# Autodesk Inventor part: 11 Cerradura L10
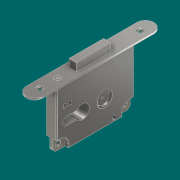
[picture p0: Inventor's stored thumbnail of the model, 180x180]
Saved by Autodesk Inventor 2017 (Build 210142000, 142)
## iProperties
Created: 2019-09
Part Number: 11 Cerradura L10
Material: Acero inoxidable
Document SubType Name: Modeling
Designer: Alfredo Castillo
Density: 8 g/cm^3
Appearance: Semipulido
Mass: 1146.85 g
Surface Area: 306.712 cm^2
Volume: 143.356 cm^3
Comments: Proveedor ITALINNEA Producto CERRADURA ADICIONAL REF. L10 CANTO REDONDO Marca AGB (ITALIA) Modelo L10 Canto Redondo Material ACERO ZINCADO Terminación BRONCE, NIQUELADA, BRONCEADA, BLACK MATT Y GRAFIT
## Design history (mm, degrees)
sketch "Boceto1"
  geometry: L1 (0, 0)-(0, 165); L2 (11, 11)-(11, 154); L3 (-11, 154)-(-11, 11); C1 r 2.75 at (0, 147.5); C2 r 2.75 at (0, 17.5); A1 r 11 centre (0, 11) between (-11, 11) and (11, 11); A2 r 11 centre (0, 154) between (11, 154) and (-11, 154); 1 further point
  constraints: 8 end point, 6 point on circle, 4 centre point, 4 point on line, 4 tangent, 1 midpoint, 1 parallel, 1 vertical
  dimensions: "d0" = 165 distance of L1.start L1.end; "d1" = 22 diameter of A2; "d2" = 5.5 diameter of C1; "d3" = 5.5 diameter of C2; "d187" = 130 distance of C2.centre C1.centre; "d188" = 17.5 distance of L1.start C2.centre
extrude "Extrusión1" new body sketch "Boceto1" distance "d6" = 3; taper "d7" = 0 deg
chamfer "Chaflán1" distance "d8" = 1.5; stored, may be unused: second distance "d9" = 2, angle "d10" = 45 deg
fillet "Empalme1" dims "d11" = 1
sketch "Boceto2"
  geometry: L1 (-7, 132.5)-(7, 132.5); L2 (7, 132.5)-(7, 32.5); L3 (7, 32.5)-(-7, 32.5); L4 (-7, 32.5)-(-7, 132.5); L5 (11, 11)-(11, 154) reference; 1 further point
  constraints: 8 end point, 2 parallel, 1 horizontal, 1 perpendicular
  dimensions: "d12" = 100 distance of L1.end L2.end; "d13" = 32.5 distance from line of point (0, 0) L3; "d16" = 14 distance of L1.start L1.end; "d17" = 4 distance between parallel lines of L5 L2
extrude "Extrusión2" join sketch "Boceto2" distance "d14" = 76; taper "d15" = 0 deg
sketch "Boceto3"
  geometry: L1 (0, 100)-(-76, 100) reference; L2 (-76, 0)-(-76, 100) reference; L3 (-76, 85)-(-76, 100); L4 (-76, 100)-(-61, 100); L5 (-76, 15)-(-76, 0); L6 (-76, 0)-(-61, 0); L7 (-76, 85)-(-71, 85); L8 (-61, 100)-(-61, 95); L9 (-76, 15)-(-71, 15); L10 (-61, 5)-(-61, 0); A1 r 10 centre (-71, 5) between (-61, 5) and (-71, 15); A2 r 10 centre (-71, 95) between (-71, 85) and (-61, 95); 1 further point
  constraints: 16 end point, 4 point on circle, 4 tangent, 3 perpendicular, 2 centre point, 2 collinear, 2 horizontal, 1 point on line, 1 vertical
  dimensions: "d254" = 5 distance of L4.end L8.end; "d255" = 10 radius of A2; "d256" = 5 distance of L3.start L7.end; "d257" = 5 distance of L5.start L9.end; "d258" = 5 distance of L10.start L6.end
extrude "Extrusión3" cut sketch "Boceto3" distance "d23" = 5; taper "d24" = 0 deg
sketch "Boceto5"
  geometry: L1 (0, 100)-(76, 100) reference; L2 (76, 100)-(76, 0) reference; L3 (61, 100)-(76, 100); L4 (76, 100)-(76, 85); L5 (76, 20)-(76, 0); L6 (76, 0)-(61, 0); L7 (0, 0)-(76, 0) reference; L8 (76, 85)-(71, 85); L9 (61, 95)-(61, 100); L10 (61, 0)-(61, 5); L11 (76, 0)-(76, 100) reference; L12 (61, 0)-(66, 0); L13 (71, 15)-(76, 15); A1 r 10 centre (71, 95) between (61, 95) and (71, 85); A2 r 10 centre (71, 5) between (71, 15) and (61, 5); 1 further point
  constraints: 18 end point, 4 point on circle, 3 collinear, 3 horizontal, 3 perpendicular, 3 point on line, 3 tangent, 2 centre point, 1 parallel
  dimensions: "d260" = 5 distance of L4.end L8.end; "d261" = 5 distance of L6.end L10.end; "d262" = 90 deg angle of L12 L10 (derived); "d263" = 5 distance of L13.start L13.end; "d264" = 10 radius of A2; "d265" = 5 distance from line of L2 A2.centre; "d266" = 5 distance of L9.start L3.start
extrude "Extrusión4" cut sketch "Boceto5" distance "d25" = 5; taper "d26" = 0 deg
fillet "Empalme2" dims "d27" = 5
hole "Agujero1" diameter "d31" = 5; stored, may be unused: countersink angle "d35" = 90 deg, drill point angle "d37" = 118 deg; dims "d29" = 7, "d30" = 7, "d32" = 6, "d33" = 4, "d34" = 2, "d36" = 8
hole "Agujero2" diameter "d40" = 5; stored, may be unused: countersink angle "d44" = 90 deg, drill point angle "d46" = 118 deg; dims "d38" = 7, "d39" = 7, "d41" = 6, "d42" = 4, "d43" = 2, "d45" = 8
fillet "Empalme4" dims "d47" = 1
fillet "Empalme5" dims "d48" = 1
fillet "Empalme6" dims "d49" = 1
fillet "Empalme7" dims "d50" = 1
sketch "Boceto37"
  geometry: L1 (-43.967, 6.834)-(-43.967, 32.334); L2 (-38.467, 12.334)-(-38.467, 25.21); L3 (-49.467, 25.21)-(-49.467, 12.334); A1 r 9 centre (-43.967, 32.334) between (-38.467, 25.21) and (-49.467, 25.21); A2 r 5.5 centre (-43.967, 12.334) between (-49.467, 12.334) and (-38.467, 12.334); 4 further points
  constraints: 8 end point, 5 point on circle, 2 centre point, 2 coincident, 2 tangent, 1 midpoint, 1 parallel, 1 point on line, 1 vertical
  dimensions: "d189" = 18 diameter of A1; "d190" = 20 distance of A2.centre A1.centre; "d191" = 10 distance of point (-43.967, 22.334) A1.centre; "d192" = 11 distance between parallel lines of L2 L3
extrude "Extrusión32" cut sketch "Boceto37" distance "d193" = 20; taper "d194" = 0 deg
sketch "Boceto38"
  geometry: L1 (-5, 105)-(5, 105); L2 (5, 105)-(5, 60); L3 (5, 60)-(-5, 60); L4 (-5, 60)-(-5, 105); L5 (11, 11)-(11, 154) reference; C1 r 2.75 at (0, 147.5) reference; 1 further point
  constraints: 8 end point, 2 parallel, 1 horizontal, 1 perpendicular
  dimensions: "d195" = 10 distance of L2.end L3.end; "d196" = 45 distance of L1.end L2.end; "d197" = 42.5 distance from line of C1.centre L1; "d198" = 6 distance between parallel lines of L5 L2
extrude "Extrusión33" join sketch "Boceto38" distance "d199" = 10; taper "d200" = 0 deg
fillet "Empalme22" dims "d201" = 0.5
sketch "Boceto39"
  geometry: L1 (5, 104.5)-(5, 60.5) reference; L2 (4.5, 60)-(-4.5, 60) reference; L3 (-5, 60.5)-(-5, 104.5) reference; L4 (-4.5, 105)-(4.5, 105) reference; L5 (11, 11)-(11, 154) reference; L6 (-11, 154)-(-11, 11) reference; L7 (4.5, 105.25)-(-4.5, 105.25); L8 (-5.25, 104.5)-(-5.25, 60.5); L9 (-4.5, 59.75)-(4.5, 59.75); L10 (5.25, 60.5)-(5.25, 104.5); C1 r 4.25 at (0, 147.5) reference; C2 r 4.25 at (0, 17.5) reference; A1 r 0.5 centre (4.5, 60.5) between (4.5, 60) and (5, 60.5) reference; A2 r 0.5 centre (-4.5, 60.5) between (-5, 60.5) and (-4.5, 60) reference; A3 r 0.5 centre (-4.5, 104.5) between (-4.5, 105) and (-5, 104.5) reference; A4 r 0.5 centre (4.5, 104.5) between (5, 104.5) and (4.5, 105) reference; A5 r 11 centre (0, 154) between (11, 154) and (-11, 154) reference; A6 r 11 centre (0, 11) between (-11, 11) and (11, 11) reference; A7 r 0.75 centre (-4.5, 104.5) between (-4.5, 105.25) and (-5.25, 104.5); A8 r 0.75 centre (-4.5, 60.5) between (-5.25, 60.5) and (-4.5, 59.75); A9 r 0.75 centre (4.5, 60.5) between (4.5, 59.75) and (5.25, 60.5); A10 r 0.75 centre (4.5, 104.5) between (5.25, 104.5) and (4.5, 105.25); 1 further point
  constraints: 8 end point, 8 point on circle, 4 centre point, 7 other
  dimensions: "d202" = 0.25 distance between parallel lines of L4 L7
extrude "Extrusión34" cut sketch "Boceto39" distance "d203" = 5; taper "d204" = 0 deg
sketch "Boceto40"
  geometry: C1 r 8 at (-43.967, 61.047); A1 r 9 centre (-43.967, 32.334) between (-38.467, 25.21) and (-49.467, 25.21) reference; 1 further point
  constraints: 1 centre point
  dimensions: "d205" = 16 diameter of C1
extrude "Extrusión35" cut sketch "Boceto40" distance "d206" = 3; taper "d207" = 0 deg
sketch "Boceto41"
  geometry: C1 r 1.5 at (0, 0); 1 further point
  constraints: 1 centre point
  dimensions: "d209" = 3 diameter of C1
extrude "Extrusión36" cut sketch "Boceto41" distance "d210" = 1; taper "d211" = 0 deg
fillet "Empalme24" dims "d212" = 1
sketch "Boceto42"
  geometry: C1 r 3.75 at (0, 40.407); C2 r 4 at (0, 40.407); 1 further point
  constraints: 2 centre point, 1 coincident
  dimensions: "d213" = 7.5 diameter of C1; "d214" = 8 diameter of C2
extrude "Extrusión37" cut sketch "Boceto42" distance "d215" = 1; taper "d216" = 0 deg
sketch "Boceto43"
  geometry: L1 (-2.006, 0.15)-(-0.661, 0.15); L2 (0.651, 0.15)-(1.994, 0.15); L3 (-2.006, -0.151)-(-0.661, -0.151); L4 (0.65, -0.15)-(1.994, -0.15); L5 (-0.161, -1.995)-(-0.161, -0.651); L6 (-0.161, 0.65)-(-0.161, 2.005); L7 (0.15, -1.996)-(0.15, -0.65); L8 (0.151, 0.65)-(0.151, 2.006); C1 r 3.75 at (0, 0) reference; A1 r 2.011 centre (0, 0) between (0.151, 2.006) and (-0.161, 2.005); A2 r 2.011 centre (0, 0) between (-2.006, 0.15) and (-2.006, -0.151); A3 r 2.002 centre (0, 0) between (-0.161, -1.995) and (0.15, -1.996); A4 r 2 centre (0, 0) between (1.994, -0.15) and (1.994, 0.15); A5 r 0.5 centre (-0.661, 0.65) between (-0.661, 0.15) and (-0.161, 0.65); A6 r 0.5 centre (0.651, 0.65) between (0.151, 0.65) and (0.651, 0.15); A7 r 0.5 centre (-0.661, -0.651) between (-0.161, -0.651) and (-0.661, -0.151); A8 r 0.5 centre (0.65, -0.65) between (0.65, -0.15) and (0.15, -0.65); 5 further points
  constraints: 16 end point, 16 point on circle, 8 centre point, 8 parallel, 8 point on line, 8 tangent, 3 equal radius, 2 horizontal, 2 vertical, 1 coincident
  dimensions: "d231" = 4 distance of L1.start L2.end; "d233" = 4 distance of L5.start L6.end; "d238" = 0.5 radius of A5
extrude "Extrusión38" cut sketch "Boceto43" distance "d236" = 1; taper "d237" = 0 deg
sketch "Boceto44"
  geometry: L1 (-51.757, 84.433)-(-46.757, 84.433); L2 (-46.757, 84.433)-(-46.757, 79.433); L3 (-46.757, 79.433)-(-51.757, 79.433); L4 (-51.757, 79.433)-(-51.757, 84.433); L5 (-71.488, 37.078)-(-68.988, 37.078); L6 (-68.988, 37.078)-(-68.988, 29.578); L7 (-68.988, 29.578)-(-71.488, 29.578); L8 (-71.488, 29.578)-(-71.488, 37.078); L9 (-23.526, 7.936)-(-28.526, 7.936); L10 (-28.526, 7.936)-(-28.526, 17.936); L11 (-28.526, 17.936)-(-23.526, 17.936); L12 (-23.526, 17.936)-(-23.526, 15.936); L13 (-23.526, 7.936)-(-23.526, 9.936); C1 r 2.5 at (-71.488, 73.201); A1 r 3.183 centre (-22.463, 12.936) between (-23.526, 15.936) and (-23.526, 9.936); 1 further point
  constraints: 26 end point, 5 perpendicular, 4 parallel, 3 horizontal, 2 centre point, 2 point on circle, 1 vertical
  dimensions: "d239" = 5 diameter of C1; "d240" = 5 distance of L2.end L3.end; "d241" = 5 distance of L1.end L2.end; "d242" = 7.5 distance of L5.end L6.end; "d243" = 5 distance of L9.start L9.end; "d244" = 10 distance of L9.end L10.end; "d245" = 2 distance of L11.end L12.end; "d246" = 2 distance of L9.start L13.end
extrude "Extrusión39" cut sketch "Boceto44" distance "d247" = 5; taper "d248" = 0 deg
fillet "Empalme25" dims "d249" = 0.5
fillet "Empalme26" dims "d250" = 0.5
fillet "Empalme27" dims "d251" = 0.5
fillet "Empalme28" dims "d252" = 0.5
fillet "Empalme29" dims "d253" = 0.5
fillet "Empalme30" dims "d259" = 1
fillet "Empalme31" dims "d267" = 1
fillet "Empalme32" dims "d268" = 1
chamfer "Chaflán2" distance "d269" = 2; stored, may be unused: second distance "d270" = 2, angle "d271" = 45 deg
fillet "Empalme33" dims "d272" = 1
node "Plano de trabajo3"
mirror "Simetría1"
fillet "Empalme34" dims "d273" = 2
sketch "Boceto45"
  geometry: L1 (-23.526, 7.936)-(-28.526, 7.936) reference; L2 (-23.526, 9.936)-(-23.526, 7.936) reference; L3 (-23.526, 17.936)-(-23.526, 15.936) reference; L4 (-28.526, 17.936)-(-23.526, 17.936) reference; L5 (-28.526, 7.936)-(-28.526, 17.936) reference; C1 r 2.5 at (-71.488, 73.201) reference; A1 r 3.183 centre (-22.463, 12.936) between (-23.526, 15.936) and (-23.526, 9.936) reference; 1 further point
extrude "Extrusión40" cut sketch "Boceto45" distance "d274" = 20; taper "d275" = 0 deg
node "Sólido1"
node "Contorno proyectado4"
node "Contorno proyectado5"
node "Contorno proyectado6"
other parameters: "d94" = 85 deg, "d232" = 0.3, "d234" = 0.3, "d235" = 4
